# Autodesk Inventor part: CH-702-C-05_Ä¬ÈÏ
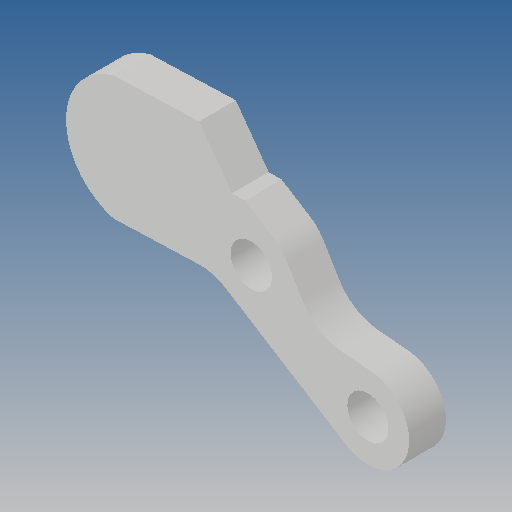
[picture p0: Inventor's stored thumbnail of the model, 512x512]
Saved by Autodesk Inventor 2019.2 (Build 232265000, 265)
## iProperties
Created: 2010-06
Part Number: CH-702-C-05_Ä¬ÈÏ
Material: Ogólny
Document SubType Name: Modeling
Designer: CADENGINEERING4
Density: 1 g/cm^3
Appearance: Domyślna
Author: CADENGINEERING4
Revision Number: ÈÎºÎ
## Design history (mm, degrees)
feature "NONE"
node "Bryła1"
